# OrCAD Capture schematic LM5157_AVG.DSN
size Custom; title: LM5157x 2.2-MHz Wide VIN Boost/Sepic/Flyback Converter with; rev: 1.0; note: Datasheet: SNVSBK7    EVM: NA; note: Synchronous Step Down Converter
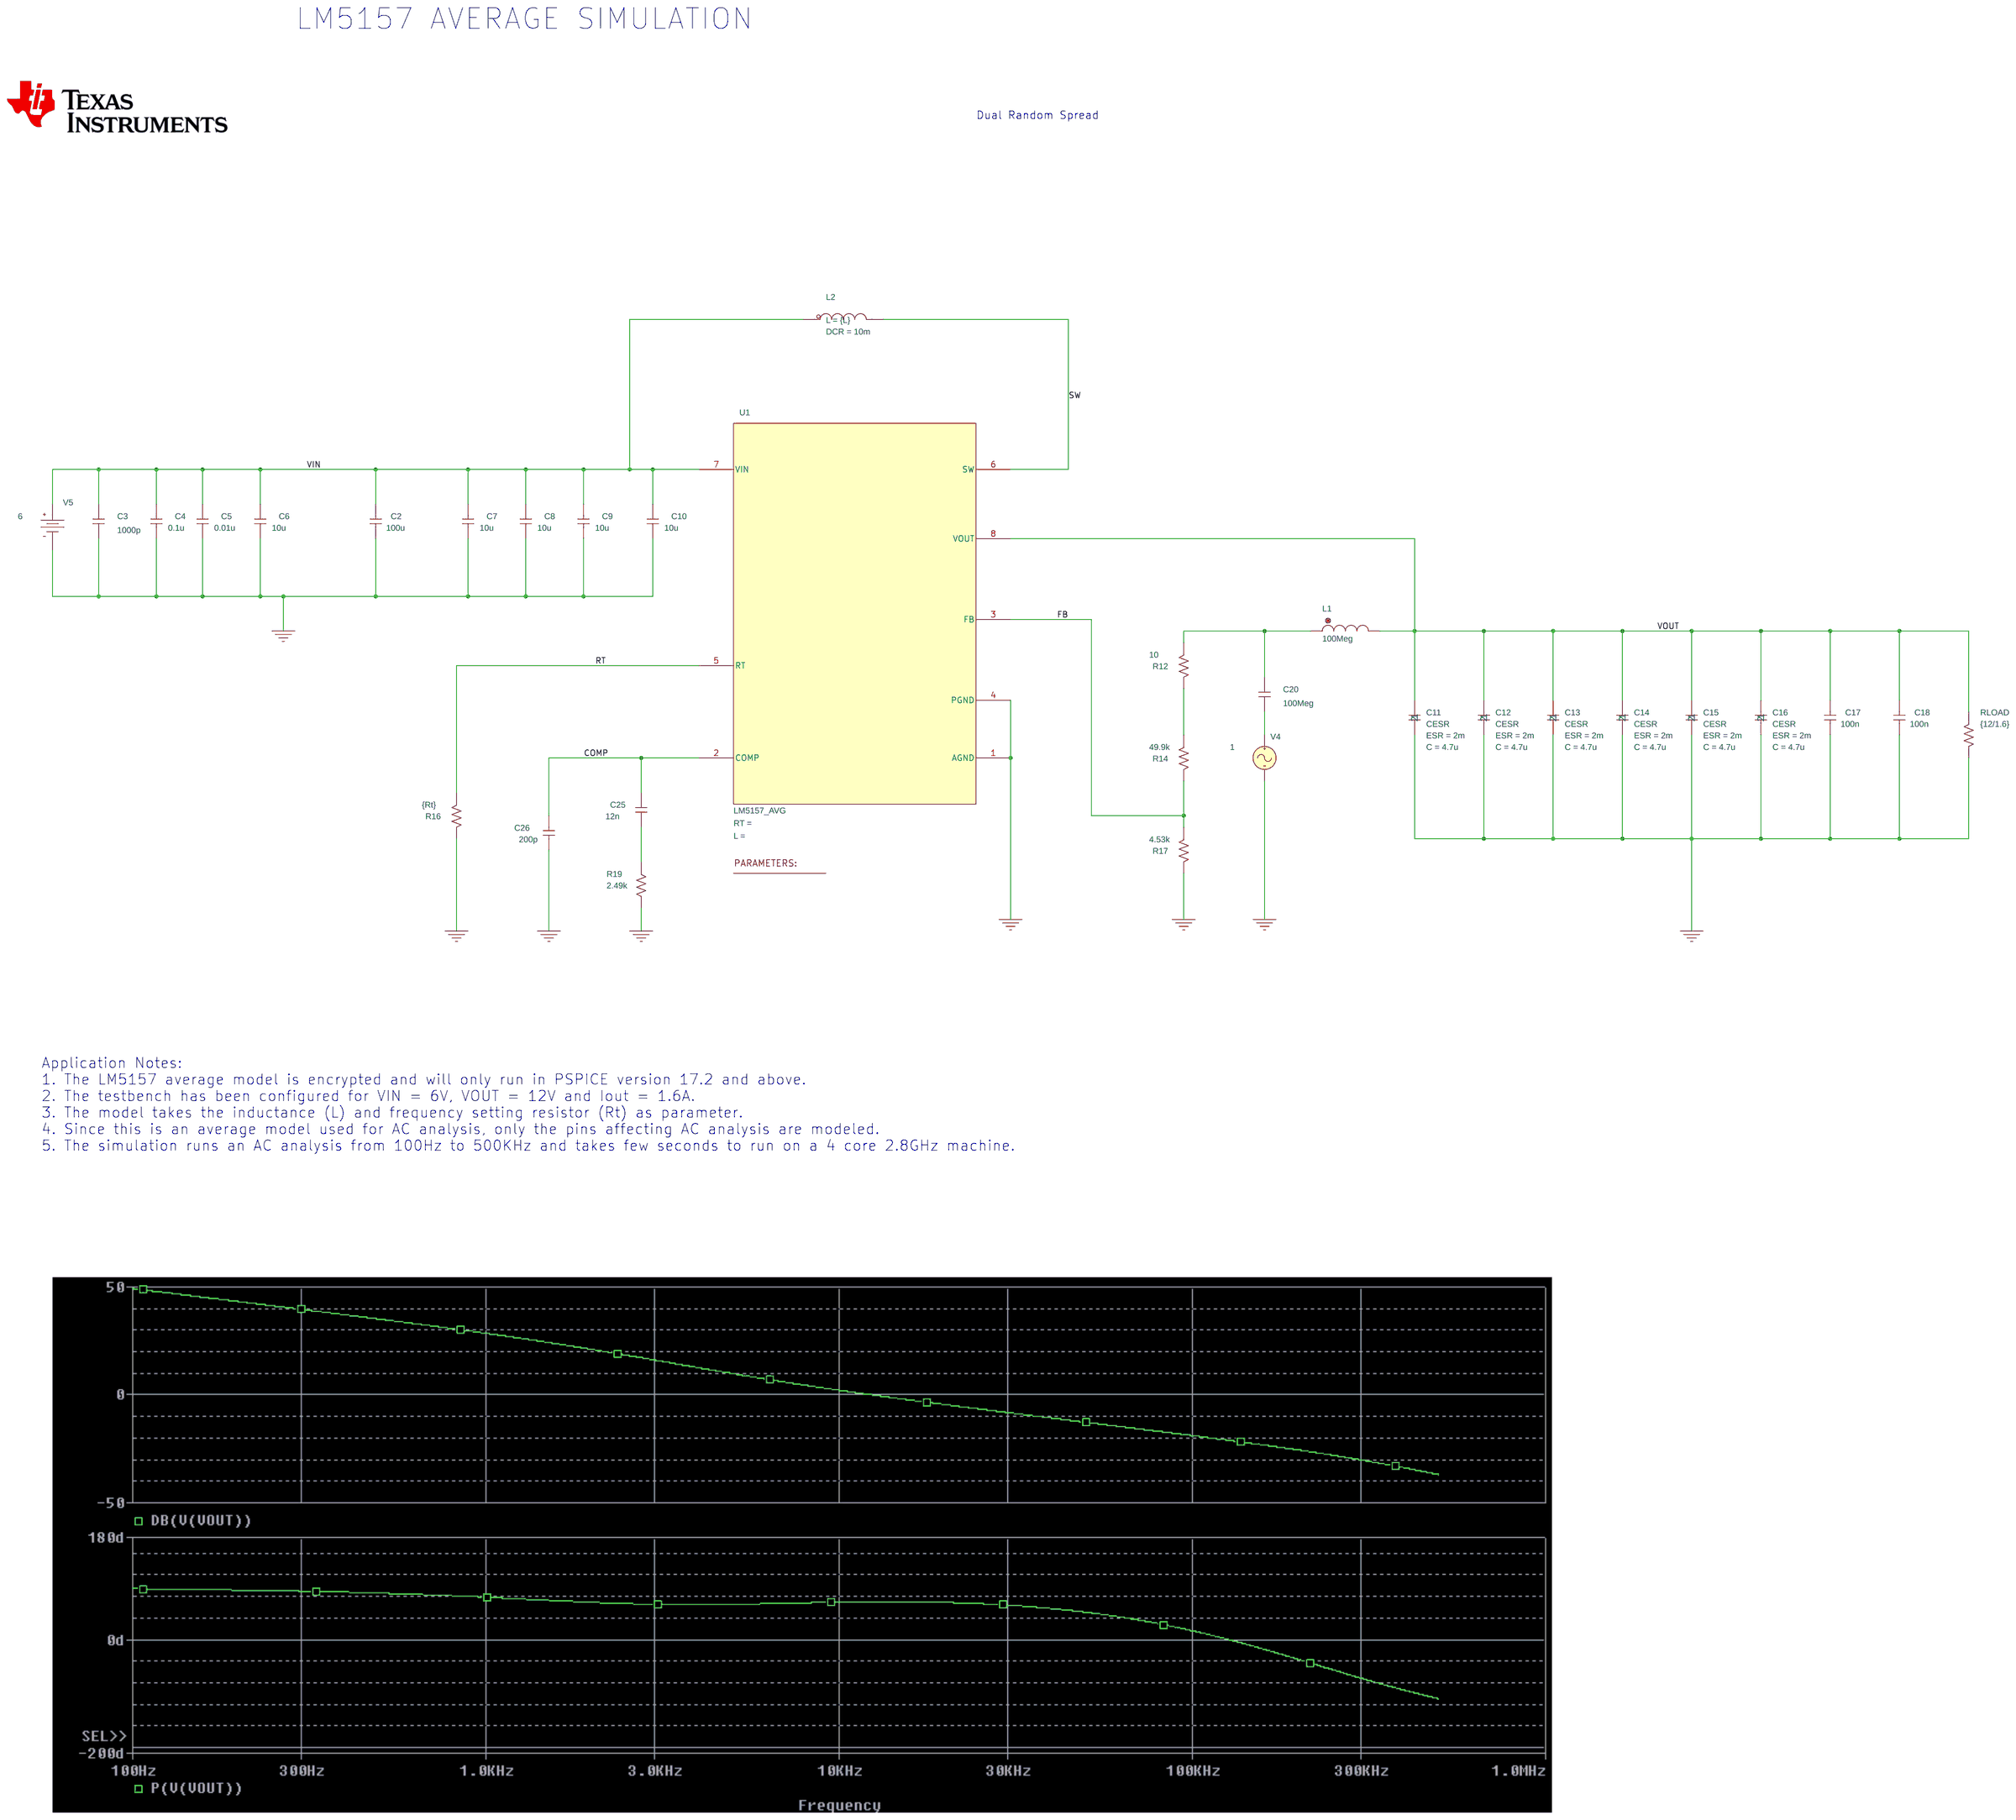
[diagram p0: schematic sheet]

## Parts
1  PARAM
C2  100u  [RAD/CK05]
C3  1000p  [RAD/CK05]
C4  0.1u  [RAD/CK05]
C5  0.01u  [RAD/CK05]
C6  10u  [RAD/CK05]
C7  10u  [RAD/CK05]
C8  10u  [RAD/CK05]
C9  10u  [RAD/CK05]
C10  10u  [RAD/CK05]
C11  CESR
C12  CESR
C13  CESR
C14  CESR
C15  CESR
C16  CESR
C17  100n  [RAD/CK05]
C18  100n  [RAD/CK05]
C20  100Meg  [RAD/CK05]
C25  12n  [RAD/CK05]
C26  200p  [RAD/CK05]
L1  100Meg  [DISC/.350x.175/LS.200x.100/.034]
L2  LDCR
R12  10  [AX/RC05]
R14  49.9k  [AX/RC05]
R16  {Rt}  [AX/RC05]
R17  4.53k  [AX/RC05]
R19  2.49k  [AX/RC05]
RLOAD  {12/1.6}  [AX/RC05]
U1  LM5157_AVG
V4  VAC
V5  VDC

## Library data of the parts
1 = PARAM: L: 1.5u; R4: 1u; R5: 100; R6: 0.008; Rt: 9.53k
C2-C10 C17 C18 C20 C25 C26 = C
C11 = CESR: C: 4.7u; ESR: 2m; PSpiceTemplate: X^@REFDES %1 %2 @MODEL PARAMS: ?C|C=@C||C=10U| ?ESR|ESR=@ESR||ESR=2M|
C12 = CESR_4: C: 4.7u; ESR: 2m; PSpiceTemplate: X^@REFDES %1 %2 @MODEL PARAMS: ?C|C=@C||C=10U| ?ESR|ESR=@ESR||ESR=2M|
C13 = CESR_1: C: 4.7u; ESR: 2m; PSpiceTemplate: X^@REFDES %1 %2 @MODEL PARAMS: ?C|C=@C||C=10U| ?ESR|ESR=@ESR||ESR=2M|
C14 = CESR_5: C: 4.7u; ESR: 2m; PSpiceTemplate: X^@REFDES %1 %2 @MODEL PARAMS: ?C|C=@C||C=10U| ?ESR|ESR=@ESR||ESR=2M|
C15 = CESR_3: C: 4.7u; ESR: 2m; PSpiceTemplate: X^@REFDES %1 %2 @MODEL PARAMS: ?C|C=@C||C=10U| ?ESR|ESR=@ESR||ESR=2M|
C16 = CESR_2: C: 4.7u; ESR: 2m; PSpiceTemplate: X^@REFDES %1 %2 @MODEL PARAMS: ?C|C=@C||C=10U| ?ESR|ESR=@ESR||ESR=2M|
L1 = L
L2 = LDCR_0: DCR: 10m; L: {L}; PSpiceTemplate: X^@REFDES %IN %OUT @MODEL PARAMS:  ?L|L=@L||L=1u|  ?DCR|DCR=@DCR||DCR=0.01|
R12 R14 R16 R17 R19 RLOAD = R
U1 = LM5157_AVG
V4 = VAC: ACMAG: 1; ACPHASE: 0
V5 = VDC: DC: 6

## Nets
VIN: C2.1 C3.1 C4.1 C5.1 C6.1 C7.1 C8.1 C9.1 C10.1 L2.1(IN) U1.7(VIN) V5.0(+)
0: C2.2 C3.2 C4.2 C5.2 C6.2 C7.2 C8.2 C9.2 C10.2 C11.2 C12.2 C13.2 C14.2 C15.2 C16.2 C17.2 C18.2 C26.2 R16.2 R17.2 R19.2 RLOAD.2 U1.1(AGND) U1.4(PGND) V4.2(-) V5.1(-)
COMP: C25.1 C26.1 U1.2(COMP)
FB: R14.2 R17.1 U1.3(FB)
RT: R16.1 U1.5(RT)
SW: L2.3(OUT) U1.6(SW)
VOUT: C11.1 C12.1 C13.1 C14.1 C15.1 C16.1 C17.1 C18.1 L1.2 RLOAD.1 U1.8(VOUT)
N299689: C20.2 V4.1(+)
N302312: C25.2 R19.1
N304851: C20.1 L1.1 R12.1
N16829923: R12.2 R14.1

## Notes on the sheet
- LM5157 AVERAGE SIMULATION
- Dual Random Spread
- Application Notes:
  1. The LM5157 average model is encrypted and will only run in PSPICE version 17.2 and above.
  2. The testbench has been configured for VIN = 6V, VOUT = 12V and Iout = 1.6A.
  3. The model takes the inductance (L) and frequency setting resistor (Rt) as parameter.
  4. Since this is an average model used for AC analysis, only the pins affecting AC analysis are modeled.
  5. The simulation runs an AC analysis from 100Hz to 500KHz and takes few seconds to run on a 4 core 2.8GHz machine.
